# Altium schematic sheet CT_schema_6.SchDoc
size 288 x 169 mm
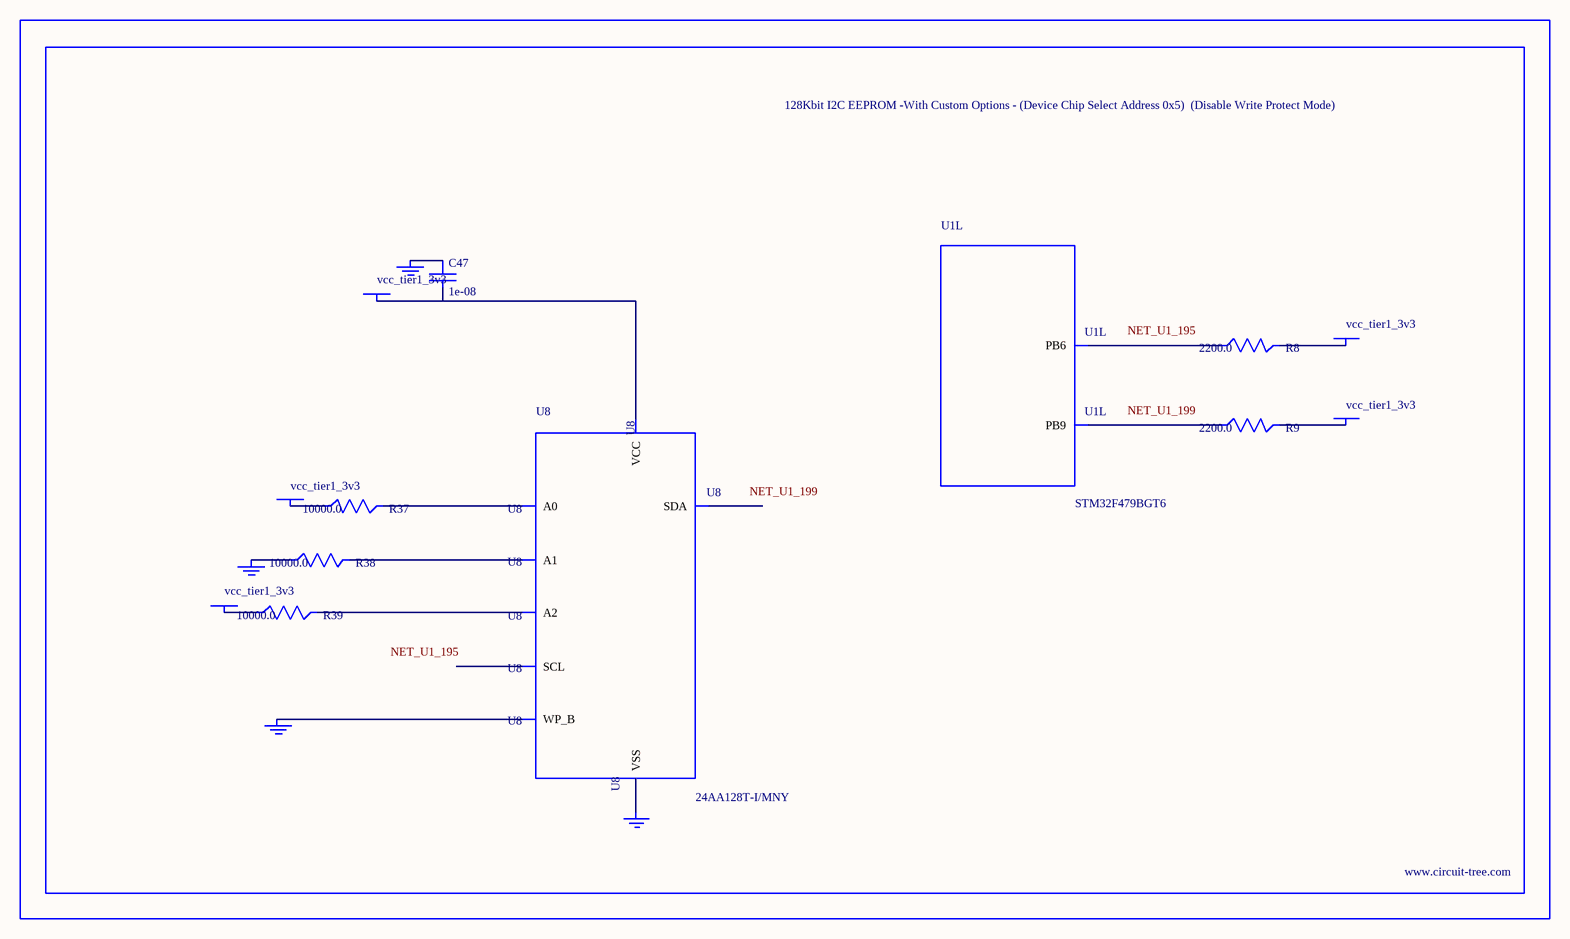
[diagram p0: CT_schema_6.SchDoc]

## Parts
BORDER5  (no value)
C47  1e-08  [C0402]
GND_INSTANCE_5_0  (no value)
GND_INSTANCE_5_1  (no value)
GND_INSTANCE_5_2  (no value)
GND_INSTANCE_5_3  (no value)
POWER_INSTANCE_5_0  vcc_tier1_3v3
POWER_INSTANCE_5_1  vcc_tier1_3v3
POWER_INSTANCE_5_2  vcc_tier1_3v3
POWER_INSTANCE_5_3  vcc_tier1_3v3
POWER_INSTANCE_5_4  vcc_tier1_3v3
R8  2200.0  [R0603]
R9  2200.0  [R0603]
R37  10000.0  [R0603]
R38  10000.0  [R0603]
R39  10000.0  [R0603]
U1  STM32F479BGT6  [LQFP208]  (part L of 16)
U8  24AA128T-I/MNY  [TDFN-8/6MM]

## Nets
NetC47_1: C47.1 GND_INSTANCE_5_2.0(GND)
NetC47_2: C47.2 POWER_INSTANCE_5_2.0(PWR) U8.8(VCC)
NetGND_INSTANCE_5_0_0: GND_INSTANCE_5_0.0(GND) R38.1
NetGND_INSTANCE_5_1_0: GND_INSTANCE_5_1.0(GND) U8.7(WP_B)
NetGND_INSTANCE_5_3_0: GND_INSTANCE_5_3.0(GND) U8.4(VSS)
NetPOWER_INSTANCE_5_0_0: POWER_INSTANCE_5_0.0(PWR) R37.1
NetPOWER_INSTANCE_5_1_0: POWER_INSTANCE_5_1.0(PWR) R39.1
NetPOWER_INSTANCE_5_3_0: POWER_INSTANCE_5_3.0(PWR) R8.2
NetPOWER_INSTANCE_5_4_0: POWER_INSTANCE_5_4.0(PWR) R9.2
NetR8_1: R8.1 U1.195(PB6)
NetR9_1: R9.1 U1.199(PB9)
NetR37_2: R37.2 U8.1(A0)
NetR38_2: R38.2 U8.2(A1)
NetR39_2: R39.2 U8.3(A2)

Not connected (* = marked no-connect by the designer): U8 5(SDA) 6(SCL)

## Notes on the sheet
- Labels drawn without touching a wire or pin: NET_U1_195, NET_U1_199

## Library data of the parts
BORDER5 = BORDER_PAGE5
C47 = C0402C103K3RAC
GND_INSTANCE_5_0-GND_INSTANCE_5_3 = GND
POWER_INSTANCE_5_0-POWER_INSTANCE_5_4 = PWR
R8 R9 = RC0603JR-072K2L
R37-R39 = RC0603JR-0710KL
